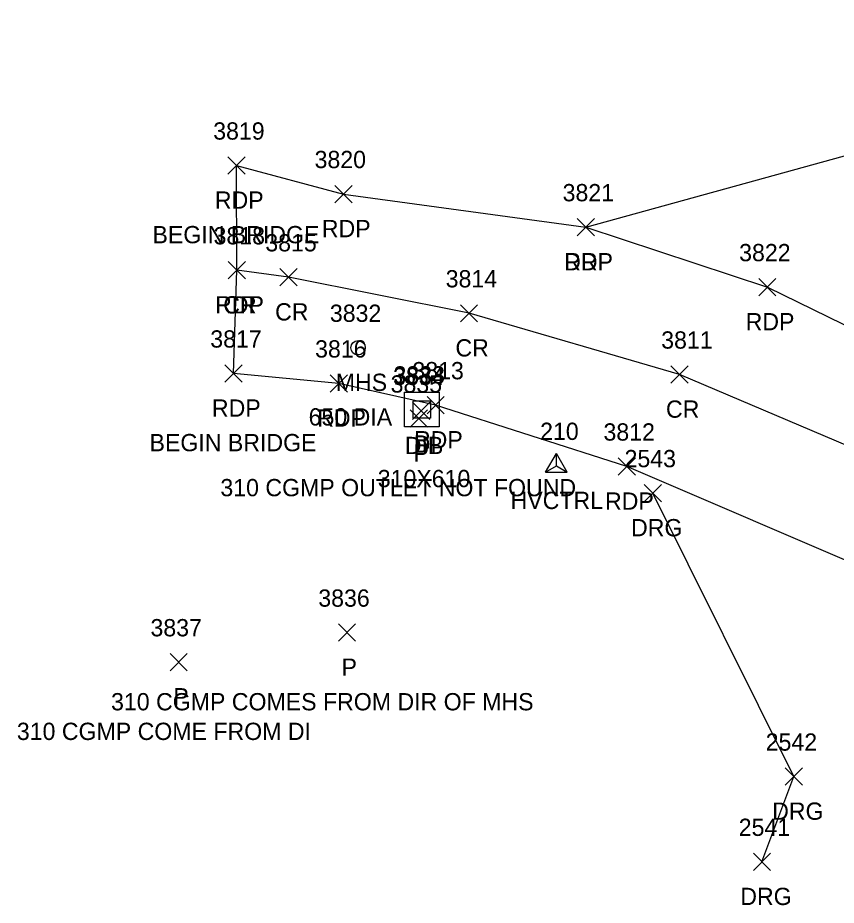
# Model space of a CAD drawing. Extents: x 1634209 to 1639641, y 608564 to 612258.
# Drawn here: x 1638711.9 to 1638806.6, y 611629.9 to 611732.6 of the extents above; entities that cross this region are included whole.
import ezdxf

# ---------------------------------------------------------------- set-up
doc = ezdxf.new("R2010")
doc.units = 0
for name, color, linetype in [('C_A', 7, 'Continuous'), ('C_I', 7, 'Continuous'), ('CPSM', 7, 'Continuous'), ('D_A', 7, 'Continuous'), ('D_C', 7, 'Continuous'), ('D_I', 7, 'Continuous'), ('D_TIC', 7, 'Continuous'), ('DS', 7, 'Continuous'), ('P_A', 7, 'Continuous'), ('P_C', 7, 'Continuous'), ('P_I', 7, 'Continuous'), ('P_TIC', 7, 'Continuous'), ('PET', 7, 'Continuous'), ('PRC', 7, 'Continuous'), ('R_A', 7, 'Continuous'), ('R_I', 7, 'Continuous'), ('R_TIC', 7, 'Continuous'), ('RDG', 7, 'Continuous'), ('RDP', 7, 'Continuous'), ('U_A', 7, 'Continuous'), ('U_C', 7, 'Continuous'), ('U_I', 7, 'Continuous'), ('USMH', 7, 'Continuous')]:
    doc.layers.add(name, color=color, linetype=linetype)

msp = doc.modelspace()

# ---------------------------------------------------------------- linework, layer by layer
at = {"layer": 'CPSM'}
for p, q in [((1638772.99, 611680.02), (1638774.24, 611682.18)), ((1638775.49, 611680.02), (1638774.24, 611682.18)), ((1638774.24, 611680.74), (1638774.24, 611682.18)), ((1638772.99, 611680.02), (1638774.24, 611680.74)), ((1638774.24, 611680.74), (1638774.24, 611680.74)), ((1638774.24, 611680.74), (1638775.49, 611680.02)), ((1638772.99, 611680.02), (1638775.49, 611680.02))]:
    msp.add_line(p, q, dxfattribs=at)
at = {"layer": 'D_TIC'}
for points in [[(1638757.6, 611686.1), (1638759.6, 611688.1)], [(1638759.6, 611686.1), (1638757.6, 611688.1)], [(1638757.32, 611685.22), (1638759.32, 611687.22)], [(1638759.32, 611685.22), (1638757.32, 611687.22)], [(1638749.01, 611660.43), (1638751.01, 611662.43)], [(1638751.01, 611660.43), (1638749.01, 611662.43)], [(1638729.53, 611657), (1638731.53, 611659)], [(1638731.53, 611657), (1638729.53, 611659)]]:
    msp.add_lwpolyline(points, dxfattribs=at)
at = {"layer": 'DS'}
for p, q in [((1638756.66, 611689.26), (1638760.66, 611689.26)), ((1638756.66, 611685.26), (1638756.66, 611689.26)), ((1638760.66, 611689.26), (1638760.66, 611685.26)), ((1638757.66, 611686.26), (1638757.66, 611688.26)), ((1638757.66, 611688.26), (1638759.66, 611688.26)), ((1638759.66, 611688.26), (1638759.66, 611686.26)), ((1638758.66, 611687.27), (1638758.66, 611687.27)), ((1638758.66, 611687.27), (1638758.66, 611687.27)), ((1638759.66, 611686.26), (1638757.66, 611686.26)), ((1638760.66, 611685.26), (1638756.66, 611685.26))]:
    msp.add_line(p, q, dxfattribs=at)
at = {"layer": 'P_TIC'}
for points in [[(1638736.23, 611714.51), (1638738.23, 611716.51)], [(1638738.23, 611714.51), (1638736.23, 611716.51)], [(1638748.61, 611711.21), (1638750.61, 611713.21)], [(1638750.61, 611711.21), (1638748.61, 611713.21)], [(1638776.65, 611707.37), (1638778.65, 611709.37)], [(1638778.65, 611707.37), (1638776.65, 611709.37)], [(1638736.26, 611702.38), (1638738.26, 611704.38)], [(1638738.26, 611702.38), (1638736.26, 611704.38)], [(1638736.26, 611702.38), (1638738.26, 611704.38)], [(1638738.26, 611702.38), (1638736.26, 611704.38)], [(1638742.25, 611701.57), (1638744.25, 611703.57)], [(1638744.25, 611701.57), (1638742.25, 611703.57)], [(1638797.65, 611700.43), (1638799.65, 611702.43)], [(1638799.65, 611700.43), (1638797.65, 611702.43)], [(1638763.13, 611697.4), (1638765.13, 611699.4)], [(1638765.13, 611697.4), (1638763.13, 611699.4)], [(1638735.89, 611690.43), (1638737.89, 611692.43)], [(1638737.89, 611690.43), (1638735.89, 611692.43)], [(1638787.49, 611690.31), (1638789.49, 611692.31)], [(1638789.49, 611690.31), (1638787.49, 611692.31)], [(1638748.07, 611689.28), (1638750.07, 611691.28)], [(1638750.07, 611689.28), (1638748.07, 611691.28)], [(1638759.27, 611686.76), (1638761.27, 611688.76)], [(1638761.27, 611686.76), (1638759.27, 611688.76)], [(1638781.38, 611679.66), (1638783.38, 611681.66)], [(1638783.38, 611679.66), (1638781.38, 611681.66)]]:
    msp.add_lwpolyline(points, dxfattribs=at)
at = {"layer": 'PET'}
msp.add_lwpolyline([(1638811.62, 611668.13), (1638782.38, 611680.66), (1638760.27, 611687.76), (1638749.07, 611690.28), (1638736.89, 611691.43), (1638737.26, 611703.38), (1638737.23, 611715.51), (1638749.61, 611712.21), (1638777.65, 611708.37), (1638798.65, 611701.43), (1638823.2, 611689.42)], dxfattribs=at)
at = {"layer": 'PRC'}
msp.add_lwpolyline([(1638816.39, 611679.45), (1638788.49, 611691.31), (1638764.13, 611698.4), (1638743.25, 611702.57), (1638737.26, 611703.38)], dxfattribs=at)
at = {"layer": 'R_TIC'}
for points in [[(1638776.65, 611707.37), (1638778.65, 611709.37)], [(1638778.65, 611707.37), (1638776.65, 611709.37)], [(1638784.39, 611676.58), (1638786.39, 611678.58)], [(1638786.39, 611676.58), (1638784.39, 611678.58)], [(1638800.72, 611643.76), (1638802.72, 611645.76)], [(1638802.72, 611643.76), (1638800.72, 611645.76)], [(1638797.03, 611633.89), (1638799.03, 611635.89)], [(1638799.03, 611633.89), (1638797.03, 611635.89)]]:
    msp.add_lwpolyline(points, dxfattribs=at)
at = {"layer": 'RDG'}
msp.add_lwpolyline([(1638798.03, 611634.89), (1638801.72, 611644.76), (1638785.39, 611677.58)], dxfattribs=at)
at = {"layer": 'RDP'}
msp.add_lwpolyline([(1638777.65, 611708.37), (1638823.65, 611721.09), (1638829.21, 611720.14), (1638839.62, 611732.62)], dxfattribs=at)
at = {"layer": 'USMH'}
for p, q in [((1638751.29, 611694.41), (1638751.29, 611694.41)), ((1638752.13, 611694.41), (1638752.13, 611694.41))]:
    msp.add_line(p, q, dxfattribs=at)
msp.add_circle((1638751.29, 611694.41), 0.833, dxfattribs=at)

# ---------------------------------------------------------------- texts
at = {"layer": 'C_A'}
msp.add_text('HVCTRL', height=2, dxfattribs=at).set_placement((1638768.94, 611675.74))
at = {"layer": 'C_I'}
msp.add_text('210', height=2, dxfattribs=at).set_placement((1638772.36, 611683.74))
at = {"layer": 'D_A'}
for s, p in [('DIB', (1638756.7, 611682.1)), ('DI', (1638757.72, 611682.27)), ('P', (1638757.7, 611681.22)), ('P', (1638749.38, 611656.43)), ('P', (1638729.91, 611653))]:
    msp.add_text(s, height=2, dxfattribs=at).set_placement(p)
at = {"layer": 'D_C'}
for s, p in [('310X610', (1638753.57, 611678.27)), ('310 CGMP OUTLET NOT FOUND', (1638735.36, 611677.22)), ('310 CGMP COMES FROM DIR OF MHS', (1638722.71, 611652.43)), ('310 CGMP COME FROM DI', (1638711.81, 611649))]:
    msp.add_text(s, height=2, dxfattribs=at).set_placement(p)
at = {"layer": 'D_I'}
for s, p in [('3834', (1638755.34, 611690.1)), ('3833', (1638755.4, 611690.27)), ('3835', (1638755.06, 611689.22)), ('3836', (1638746.69, 611664.43)), ('3837', (1638727.27, 611661))]:
    msp.add_text(s, height=2, dxfattribs=at).set_placement(p)
at = {"layer": 'P_A'}
for s, p in [('RDP', (1638734.72, 611710.51)), ('RDP', (1638747.1, 611707.21)), ('RDP', (1638775.14, 611703.37)), ('RDP', (1638734.75, 611698.38)), ('CR', (1638735.69, 611698.38)), ('CR', (1638741.69, 611697.57)), ('RDP', (1638796.14, 611696.43)), ('CR', (1638762.56, 611693.4)), ('RDP', (1638734.38, 611686.43)), ('CR', (1638786.92, 611686.31)), ('RDP', (1638746.56, 611685.28)), ('RDP', (1638757.76, 611682.76)), ('RDP', (1638779.87, 611675.66))]:
    msp.add_text(s, height=2, dxfattribs=at).set_placement(p)
at = {"layer": 'P_C'}
for p in [(1638727.5, 611706.51), (1638727.16, 611682.43)]:
    msp.add_text('BEGIN BRIDGE', height=2, dxfattribs=at).set_placement(p)
at = {"layer": 'P_I'}
for s, p in [('3819', (1638734.53, 611718.51)), ('3820', (1638746.26, 611715.21)), ('3821', (1638774.96, 611711.37)), ('3818', (1638734.57, 611706.38)), ('3818', (1638734.57, 611706.38)), ('3815', (1638740.56, 611705.57)), ('3822', (1638795.39, 611704.43)), ('3814', (1638761.43, 611701.4)), ('3817', (1638734.19, 611694.43)), ('3811', (1638786.37, 611694.31)), ('3816', (1638746.32, 611693.28)), ('3813', (1638757.58, 611690.76)), ('3812', (1638779.69, 611683.66))]:
    msp.add_text(s, height=2, dxfattribs=at).set_placement(p)
at = {"layer": 'R_A'}
for s, p in [('DRP', (1638775.14, 611703.37)), ('DRG', (1638782.88, 611672.58)), ('DRG', (1638799.21, 611639.76)), ('DRG', (1638795.52, 611629.89))]:
    msp.add_text(s, height=2, dxfattribs=at).set_placement(p)
at = {"layer": 'R_I'}
for s, p in [('3821', (1638774.96, 611711.37)), ('2543', (1638782.13, 611680.58)), ('2542', (1638798.46, 611647.76)), ('2541', (1638795.34, 611637.89))]:
    msp.add_text(s, height=2, dxfattribs=at).set_placement(p)
at = {"layer": 'U_A'}
msp.add_text('MHS', height=2, dxfattribs=at).set_placement((1638748.71, 611689.41))
at = {"layer": 'U_C'}
msp.add_text('650 DIA', height=2, dxfattribs=at).set_placement((1638745.57, 611685.41))
at = {"layer": 'U_I'}
msp.add_text('3832', height=2, dxfattribs=at).set_placement((1638748.03, 611697.41))

doc.saveas('drawing.dxf')
